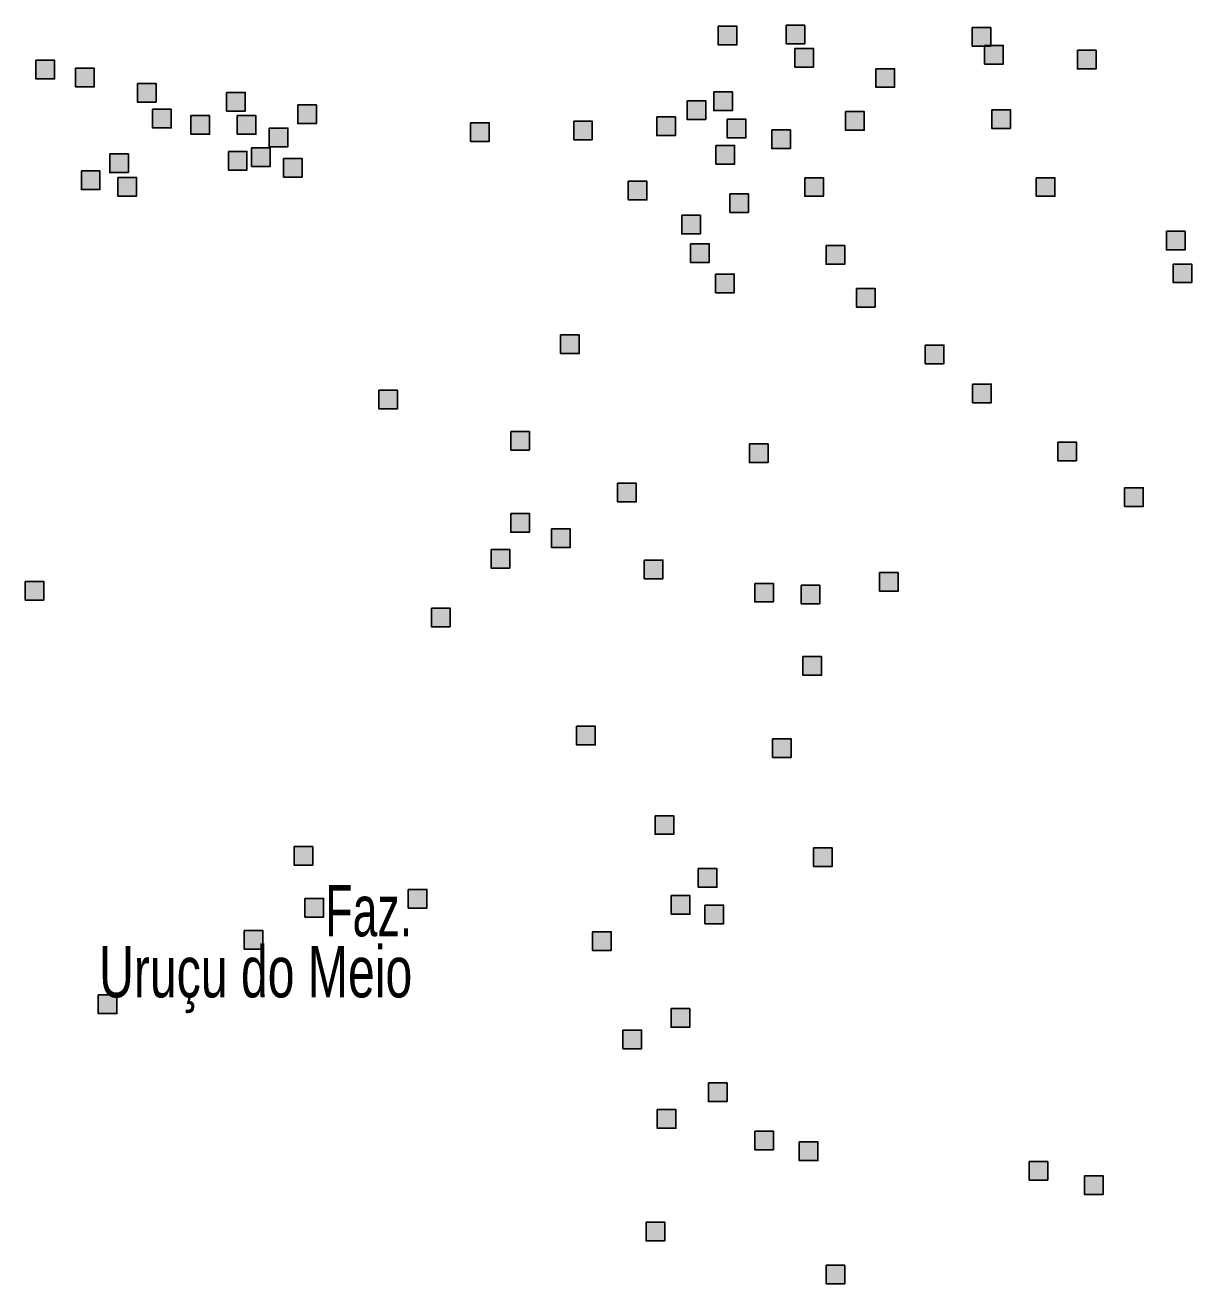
# Model space of a CAD drawing. Extents: x 445.6 to 500, y 8618.1 to 8673.4.
# Drawn here: x 460.751 to 464.38, y 8626.549 to 8630.464 of the extents above; entities that cross this region are included whole.
import ezdxf
from ezdxf.enums import TextEntityAlignment as Align

# ---------------------------------------------------------------- set-up
doc = ezdxf.new("R2010")
doc.units = 0
doc.header["$LTSCALE"] = 0.064
doc.layers.add('2', color=7, linetype='Continuous', lineweight=25)
doc.layers.add('61', color=7, linetype='Continuous')

msp = doc.modelspace()

# ---------------------------------------------------------------- hatches: boundary and pattern name
at = {"layer": '2'}
for points in [[(462.9071, 8630.4607), (462.9651, 8630.4607), (462.9651, 8630.4027), (462.9071, 8630.4027)], [(463.1178, 8630.4641), (463.1758, 8630.4641), (463.1758, 8630.4061), (463.1178, 8630.4061)], [(463.6966, 8630.4567), (463.7546, 8630.4567), (463.7546, 8630.3987), (463.6966, 8630.3987)], [(463.1455, 8630.3919), (463.2035, 8630.3919), (463.2035, 8630.3339), (463.1455, 8630.3339)], [(463.7354, 8630.4011), (463.7934, 8630.4011), (463.7934, 8630.3431), (463.7354, 8630.3431)], [(464.0241, 8630.3862), (464.0821, 8630.3862), (464.0821, 8630.3282), (464.0241, 8630.3282)], [(460.7846, 8630.3551), (460.8426, 8630.3551), (460.8426, 8630.2971), (460.7846, 8630.2971)], [(460.9081, 8630.3303), (460.9661, 8630.3303), (460.9661, 8630.2723), (460.9081, 8630.2723)], [(463.3973, 8630.3288), (463.4553, 8630.3288), (463.4553, 8630.2708), (463.3973, 8630.2708)], [(461.1005, 8630.2828), (461.1585, 8630.2828), (461.1585, 8630.2248), (461.1005, 8630.2248)], [(461.3776, 8630.255), (461.4356, 8630.255), (461.4356, 8630.197), (461.3776, 8630.197)], [(462.893, 8630.2566), (462.951, 8630.2566), (462.951, 8630.1986), (462.893, 8630.1986)], [(461.5992, 8630.2161), (461.6572, 8630.2161), (461.6572, 8630.1581), (461.5992, 8630.1581)], [(462.8099, 8630.2288), (462.8679, 8630.2288), (462.8679, 8630.1708), (462.8099, 8630.1708)], [(461.1473, 8630.2027), (461.2053, 8630.2027), (461.2053, 8630.1447), (461.1473, 8630.1447)], [(461.2667, 8630.1828), (461.3247, 8630.1828), (461.3247, 8630.1248), (461.2667, 8630.1248)], [(461.4108, 8630.1828), (461.4688, 8630.1828), (461.4688, 8630.1248), (461.4108, 8630.1248)], [(462.7157, 8630.1788), (462.7737, 8630.1788), (462.7737, 8630.1208), (462.7157, 8630.1208)], [(462.9348, 8630.1717), (462.9928, 8630.1717), (462.9928, 8630.1137), (462.9348, 8630.1137)], [(463.3031, 8630.1955), (463.3611, 8630.1955), (463.3611, 8630.1375), (463.3031, 8630.1375)], [(463.7575, 8630.201), (463.8155, 8630.201), (463.8155, 8630.143), (463.7575, 8630.143)], [(461.5106, 8630.1439), (461.5686, 8630.1439), (461.5686, 8630.0859), (461.5106, 8630.0859)], [(462.1368, 8630.1605), (462.1948, 8630.1605), (462.1948, 8630.1025), (462.1368, 8630.1025)], [(462.4572, 8630.1655), (462.5152, 8630.1655), (462.5152, 8630.1075), (462.4572, 8630.1075)], [(463.0733, 8630.1383), (463.1313, 8630.1383), (463.1313, 8630.0803), (463.0733, 8630.0803)], [(462.8998, 8630.0902), (462.9578, 8630.0902), (462.9578, 8630.0322), (462.8998, 8630.0322)], [(461.0143, 8630.0637), (461.0723, 8630.0637), (461.0723, 8630.0057), (461.0143, 8630.0057)], [(461.3831, 8630.0716), (461.4411, 8630.0716), (461.4411, 8630.0136), (461.3831, 8630.0136)], [(461.4552, 8630.0827), (461.5132, 8630.0827), (461.5132, 8630.0247), (461.4552, 8630.0247)], [(461.5549, 8630.0494), (461.6129, 8630.0494), (461.6129, 8629.9914), (461.5549, 8629.9914)], [(460.9259, 8630.0106), (460.9839, 8630.0106), (460.9839, 8629.9526), (460.9259, 8629.9526)], [(461.0399, 8629.9904), (461.0979, 8629.9904), (461.0979, 8629.9324), (461.0399, 8629.9324)], [(462.627, 8629.9787), (462.685, 8629.9787), (462.685, 8629.9207), (462.627, 8629.9207)], [(463.1757, 8629.9898), (463.2337, 8629.9898), (463.2337, 8629.9318), (463.1757, 8629.9318)], [(463.8961, 8629.9898), (463.9541, 8629.9898), (463.9541, 8629.9318), (463.8961, 8629.9318)], [(462.9429, 8629.9398), (463.0009, 8629.9398), (463.0009, 8629.8818), (462.9429, 8629.8818)], [(462.7933, 8629.8731), (462.8513, 8629.8731), (462.8513, 8629.8151), (462.7933, 8629.8151)], [(464.3006, 8629.8231), (464.3586, 8629.8231), (464.3586, 8629.7651), (464.3006, 8629.7651)], [(462.821, 8629.7842), (462.879, 8629.7842), (462.879, 8629.7262), (462.821, 8629.7262)], [(463.2422, 8629.7786), (463.3002, 8629.7786), (463.3002, 8629.7206), (463.2422, 8629.7206)], [(464.3218, 8629.7213), (464.3798, 8629.7213), (464.3798, 8629.6633), (464.3218, 8629.6633)], [(462.8986, 8629.6897), (462.9566, 8629.6897), (462.9566, 8629.6317), (462.8986, 8629.6317)], [(463.3364, 8629.6452), (463.3944, 8629.6452), (463.3944, 8629.5872), (463.3364, 8629.5872)], [(462.4164, 8629.5007), (462.4744, 8629.5007), (462.4744, 8629.4427), (462.4164, 8629.4427)], [(463.5506, 8629.4691), (463.6086, 8629.4691), (463.6086, 8629.4111), (463.5506, 8629.4111)], [(463.6981, 8629.348), (463.7561, 8629.348), (463.7561, 8629.29), (463.6981, 8629.29)], [(461.8512, 8629.3284), (461.9092, 8629.3284), (461.9092, 8629.2704), (461.8512, 8629.2704)], [(462.2613, 8629.2005), (462.3193, 8629.2005), (462.3193, 8629.1425), (462.2613, 8629.1425)], [(463.0039, 8629.1616), (463.0619, 8629.1616), (463.0619, 8629.1036), (463.0039, 8629.1036)], [(463.9626, 8629.1672), (464.0206, 8629.1672), (464.0206, 8629.1092), (463.9626, 8629.1092)], [(462.5938, 8629.0394), (462.6518, 8629.0394), (462.6518, 8628.9814), (462.5938, 8628.9814)], [(464.1709, 8629.0252), (464.2289, 8629.0252), (464.2289, 8628.9672), (464.1709, 8628.9672)], [(462.2613, 8628.9449), (462.3193, 8628.9449), (462.3193, 8628.8869), (462.2613, 8628.8869)], [(462.3887, 8628.8974), (462.4467, 8628.8974), (462.4467, 8628.8394), (462.3887, 8628.8394)], [(462.2003, 8628.8337), (462.2583, 8628.8337), (462.2583, 8628.7757), (462.2003, 8628.7757)], [(462.6769, 8628.8004), (462.7349, 8628.8004), (462.7349, 8628.7424), (462.6769, 8628.7424)], [(463.4084, 8628.7615), (463.4664, 8628.7615), (463.4664, 8628.7035), (463.4084, 8628.7035)], [(460.7512, 8628.7341), (460.8092, 8628.7341), (460.8092, 8628.6761), (460.7512, 8628.6761)], [(463.0205, 8628.7281), (463.0785, 8628.7281), (463.0785, 8628.6701), (463.0205, 8628.6701)], [(463.1646, 8628.7225), (463.2226, 8628.7225), (463.2226, 8628.6645), (463.1646, 8628.6645)], [(462.0147, 8628.6512), (462.0727, 8628.6512), (462.0727, 8628.5932), (462.0147, 8628.5932)], [(463.1701, 8628.5002), (463.2281, 8628.5002), (463.2281, 8628.4422), (463.1701, 8628.4422)], [(462.4663, 8628.2835), (462.5243, 8628.2835), (462.5243, 8628.2255), (462.4663, 8628.2255)], [(463.0759, 8628.2445), (463.1339, 8628.2445), (463.1339, 8628.1865), (463.0759, 8628.1865)], [(462.7102, 8628.0055), (462.7682, 8628.0055), (462.7682, 8627.9475), (462.7102, 8627.9475)], [(461.5879, 8627.9094), (461.6459, 8627.9094), (461.6459, 8627.8514), (461.5879, 8627.8514)], [(463.2034, 8627.9055), (463.2614, 8627.9055), (463.2614, 8627.8475), (463.2034, 8627.8475)], [(462.8446, 8627.8411), (462.9026, 8627.8411), (462.9026, 8627.7831), (462.8446, 8627.7831)], [(461.6211, 8627.7482), (461.6791, 8627.7482), (461.6791, 8627.6902), (461.6211, 8627.6902)], [(461.9425, 8627.776), (462.0005, 8627.776), (462.0005, 8627.718), (461.9425, 8627.718)], [(462.7608, 8627.7571), (462.8188, 8627.7571), (462.8188, 8627.6991), (462.7608, 8627.6991)], [(462.8653, 8627.7276), (462.9233, 8627.7276), (462.9233, 8627.6696), (462.8653, 8627.6696)], [(461.4327, 8627.6482), (461.4907, 8627.6482), (461.4907, 8627.5902), (461.4327, 8627.5902)], [(462.5162, 8627.6443), (462.5742, 8627.6443), (462.5742, 8627.5863), (462.5162, 8627.5863)], [(460.9783, 8627.4481), (461.0363, 8627.4481), (461.0363, 8627.3901), (460.9783, 8627.3901)], [(462.76, 8627.4053), (462.818, 8627.4053), (462.818, 8627.3473), (462.76, 8627.3473)], [(462.6104, 8627.3386), (462.6684, 8627.3386), (462.6684, 8627.2806), (462.6104, 8627.2806)], [(462.8764, 8627.1744), (462.9344, 8627.1744), (462.9344, 8627.1164), (462.8764, 8627.1164)], [(462.7172, 8627.0912), (462.7752, 8627.0912), (462.7752, 8627.0332), (462.7172, 8627.0332)], [(463.0205, 8627.0243), (463.0785, 8627.0243), (463.0785, 8626.9663), (463.0205, 8626.9663)], [(463.159, 8626.991), (463.217, 8626.991), (463.217, 8626.933), (463.159, 8626.933)], [(463.8739, 8626.9299), (463.9319, 8626.9299), (463.9319, 8626.8719), (463.8739, 8626.8719)], [(464.0457, 8626.8854), (464.1037, 8626.8854), (464.1037, 8626.8274), (464.0457, 8626.8274)], [(462.6824, 8626.7409), (462.7404, 8626.7409), (462.7404, 8626.6829), (462.6824, 8626.6829)], [(463.2422, 8626.6075), (463.3002, 8626.6075), (463.3002, 8626.5495), (463.2422, 8626.5495)]]:
    msp.add_hatch(color=256, dxfattribs=at).paths.add_polyline_path(points)

# ---------------------------------------------------------------- linework, layer by layer
for points in [[(462.9071, 8630.4607), (462.9651, 8630.4607), (462.9651, 8630.4027), (462.9071, 8630.4027)], [(463.1178, 8630.4641), (463.1758, 8630.4641), (463.1758, 8630.4061), (463.1178, 8630.4061)], [(463.6966, 8630.4567), (463.7546, 8630.4567), (463.7546, 8630.3987), (463.6966, 8630.3987)], [(463.1455, 8630.3919), (463.2035, 8630.3919), (463.2035, 8630.3339), (463.1455, 8630.3339)], [(463.7354, 8630.4011), (463.7934, 8630.4011), (463.7934, 8630.3431), (463.7354, 8630.3431)], [(464.0241, 8630.3862), (464.0821, 8630.3862), (464.0821, 8630.3282), (464.0241, 8630.3282)], [(460.7846, 8630.3551), (460.8426, 8630.3551), (460.8426, 8630.2971), (460.7846, 8630.2971)], [(460.9081, 8630.3303), (460.9661, 8630.3303), (460.9661, 8630.2723), (460.9081, 8630.2723)], [(463.3973, 8630.3288), (463.4553, 8630.3288), (463.4553, 8630.2708), (463.3973, 8630.2708)], [(461.1005, 8630.2828), (461.1585, 8630.2828), (461.1585, 8630.2248), (461.1005, 8630.2248)], [(461.3776, 8630.255), (461.4356, 8630.255), (461.4356, 8630.197), (461.3776, 8630.197)], [(462.893, 8630.2566), (462.951, 8630.2566), (462.951, 8630.1986), (462.893, 8630.1986)], [(461.5992, 8630.2161), (461.6572, 8630.2161), (461.6572, 8630.1581), (461.5992, 8630.1581)], [(462.8099, 8630.2288), (462.8679, 8630.2288), (462.8679, 8630.1708), (462.8099, 8630.1708)], [(461.1473, 8630.2027), (461.2053, 8630.2027), (461.2053, 8630.1447), (461.1473, 8630.1447)], [(461.2667, 8630.1828), (461.3247, 8630.1828), (461.3247, 8630.1248), (461.2667, 8630.1248)], [(461.4108, 8630.1828), (461.4688, 8630.1828), (461.4688, 8630.1248), (461.4108, 8630.1248)], [(462.7157, 8630.1788), (462.7737, 8630.1788), (462.7737, 8630.1208), (462.7157, 8630.1208)], [(462.9348, 8630.1717), (462.9928, 8630.1717), (462.9928, 8630.1137), (462.9348, 8630.1137)], [(463.3031, 8630.1955), (463.3611, 8630.1955), (463.3611, 8630.1375), (463.3031, 8630.1375)], [(463.7575, 8630.201), (463.8155, 8630.201), (463.8155, 8630.143), (463.7575, 8630.143)], [(461.5106, 8630.1439), (461.5686, 8630.1439), (461.5686, 8630.0859), (461.5106, 8630.0859)], [(462.1368, 8630.1605), (462.1948, 8630.1605), (462.1948, 8630.1025), (462.1368, 8630.1025)], [(462.4572, 8630.1655), (462.5152, 8630.1655), (462.5152, 8630.1075), (462.4572, 8630.1075)], [(463.0733, 8630.1383), (463.1313, 8630.1383), (463.1313, 8630.0803), (463.0733, 8630.0803)], [(462.8998, 8630.0902), (462.9578, 8630.0902), (462.9578, 8630.0322), (462.8998, 8630.0322)], [(461.0143, 8630.0637), (461.0723, 8630.0637), (461.0723, 8630.0057), (461.0143, 8630.0057)], [(461.3831, 8630.0716), (461.4411, 8630.0716), (461.4411, 8630.0136), (461.3831, 8630.0136)], [(461.4552, 8630.0827), (461.5132, 8630.0827), (461.5132, 8630.0247), (461.4552, 8630.0247)], [(461.5549, 8630.0494), (461.6129, 8630.0494), (461.6129, 8629.9914), (461.5549, 8629.9914)], [(460.9259, 8630.0106), (460.9839, 8630.0106), (460.9839, 8629.9526), (460.9259, 8629.9526)], [(461.0399, 8629.9904), (461.0979, 8629.9904), (461.0979, 8629.9324), (461.0399, 8629.9324)], [(462.627, 8629.9787), (462.685, 8629.9787), (462.685, 8629.9207), (462.627, 8629.9207)], [(463.1757, 8629.9898), (463.2337, 8629.9898), (463.2337, 8629.9318), (463.1757, 8629.9318)], [(463.8961, 8629.9898), (463.9541, 8629.9898), (463.9541, 8629.9318), (463.8961, 8629.9318)], [(462.9429, 8629.9398), (463.0009, 8629.9398), (463.0009, 8629.8818), (462.9429, 8629.8818)], [(462.7933, 8629.8731), (462.8513, 8629.8731), (462.8513, 8629.8151), (462.7933, 8629.8151)], [(464.3006, 8629.8231), (464.3586, 8629.8231), (464.3586, 8629.7651), (464.3006, 8629.7651)], [(462.821, 8629.7842), (462.879, 8629.7842), (462.879, 8629.7262), (462.821, 8629.7262)], [(463.2422, 8629.7786), (463.3002, 8629.7786), (463.3002, 8629.7206), (463.2422, 8629.7206)], [(464.3218, 8629.7213), (464.3798, 8629.7213), (464.3798, 8629.6633), (464.3218, 8629.6633)], [(462.8986, 8629.6897), (462.9566, 8629.6897), (462.9566, 8629.6317), (462.8986, 8629.6317)], [(463.3364, 8629.6452), (463.3944, 8629.6452), (463.3944, 8629.5872), (463.3364, 8629.5872)], [(462.4164, 8629.5007), (462.4744, 8629.5007), (462.4744, 8629.4427), (462.4164, 8629.4427)], [(463.5506, 8629.4691), (463.6086, 8629.4691), (463.6086, 8629.4111), (463.5506, 8629.4111)], [(463.6981, 8629.348), (463.7561, 8629.348), (463.7561, 8629.29), (463.6981, 8629.29)], [(461.8512, 8629.3284), (461.9092, 8629.3284), (461.9092, 8629.2704), (461.8512, 8629.2704)], [(462.2613, 8629.2005), (462.3193, 8629.2005), (462.3193, 8629.1425), (462.2613, 8629.1425)], [(463.0039, 8629.1616), (463.0619, 8629.1616), (463.0619, 8629.1036), (463.0039, 8629.1036)], [(463.9626, 8629.1672), (464.0206, 8629.1672), (464.0206, 8629.1092), (463.9626, 8629.1092)], [(462.5938, 8629.0394), (462.6518, 8629.0394), (462.6518, 8628.9814), (462.5938, 8628.9814)], [(464.1709, 8629.0252), (464.2289, 8629.0252), (464.2289, 8628.9672), (464.1709, 8628.9672)], [(462.2613, 8628.9449), (462.3193, 8628.9449), (462.3193, 8628.8869), (462.2613, 8628.8869)], [(462.3887, 8628.8974), (462.4467, 8628.8974), (462.4467, 8628.8394), (462.3887, 8628.8394)], [(462.2003, 8628.8337), (462.2583, 8628.8337), (462.2583, 8628.7757), (462.2003, 8628.7757)], [(462.6769, 8628.8004), (462.7349, 8628.8004), (462.7349, 8628.7424), (462.6769, 8628.7424)], [(463.4084, 8628.7615), (463.4664, 8628.7615), (463.4664, 8628.7035), (463.4084, 8628.7035)], [(460.7512, 8628.7341), (460.8092, 8628.7341), (460.8092, 8628.6761), (460.7512, 8628.6761)], [(463.0205, 8628.7281), (463.0785, 8628.7281), (463.0785, 8628.6701), (463.0205, 8628.6701)], [(463.1646, 8628.7225), (463.2226, 8628.7225), (463.2226, 8628.6645), (463.1646, 8628.6645)], [(462.0147, 8628.6512), (462.0727, 8628.6512), (462.0727, 8628.5932), (462.0147, 8628.5932)], [(463.1701, 8628.5002), (463.2281, 8628.5002), (463.2281, 8628.4422), (463.1701, 8628.4422)], [(462.4663, 8628.2835), (462.5243, 8628.2835), (462.5243, 8628.2255), (462.4663, 8628.2255)], [(463.0759, 8628.2445), (463.1339, 8628.2445), (463.1339, 8628.1865), (463.0759, 8628.1865)], [(462.7102, 8628.0055), (462.7682, 8628.0055), (462.7682, 8627.9475), (462.7102, 8627.9475)], [(461.5879, 8627.9094), (461.6459, 8627.9094), (461.6459, 8627.8514), (461.5879, 8627.8514)], [(463.2034, 8627.9055), (463.2614, 8627.9055), (463.2614, 8627.8475), (463.2034, 8627.8475)], [(462.8446, 8627.8411), (462.9026, 8627.8411), (462.9026, 8627.7831), (462.8446, 8627.7831)], [(461.6211, 8627.7482), (461.6791, 8627.7482), (461.6791, 8627.6902), (461.6211, 8627.6902)], [(461.9425, 8627.776), (462.0005, 8627.776), (462.0005, 8627.718), (461.9425, 8627.718)], [(462.7608, 8627.7571), (462.8188, 8627.7571), (462.8188, 8627.6991), (462.7608, 8627.6991)], [(462.8653, 8627.7276), (462.9233, 8627.7276), (462.9233, 8627.6696), (462.8653, 8627.6696)], [(461.4327, 8627.6482), (461.4907, 8627.6482), (461.4907, 8627.5902), (461.4327, 8627.5902)], [(462.5162, 8627.6443), (462.5742, 8627.6443), (462.5742, 8627.5863), (462.5162, 8627.5863)], [(460.9783, 8627.4481), (461.0363, 8627.4481), (461.0363, 8627.3901), (460.9783, 8627.3901)], [(462.76, 8627.4053), (462.818, 8627.4053), (462.818, 8627.3473), (462.76, 8627.3473)], [(462.6104, 8627.3386), (462.6684, 8627.3386), (462.6684, 8627.2806), (462.6104, 8627.2806)], [(462.8764, 8627.1744), (462.9344, 8627.1744), (462.9344, 8627.1164), (462.8764, 8627.1164)], [(462.7172, 8627.0912), (462.7752, 8627.0912), (462.7752, 8627.0332), (462.7172, 8627.0332)], [(463.0205, 8627.0243), (463.0785, 8627.0243), (463.0785, 8626.9663), (463.0205, 8626.9663)], [(463.159, 8626.991), (463.217, 8626.991), (463.217, 8626.933), (463.159, 8626.933)], [(463.8739, 8626.9299), (463.9319, 8626.9299), (463.9319, 8626.8719), (463.8739, 8626.8719)], [(464.0457, 8626.8854), (464.1037, 8626.8854), (464.1037, 8626.8274), (464.0457, 8626.8274)], [(462.6824, 8626.7409), (462.7404, 8626.7409), (462.7404, 8626.6829), (462.6824, 8626.6829)], [(463.2422, 8626.6075), (463.3002, 8626.6075), (463.3002, 8626.5495), (463.2422, 8626.5495)]]:
    msp.add_lwpolyline(points, close=True, dxfattribs=at)

# ---------------------------------------------------------------- texts
at = {"layer": '61'}
for s, width, p in [('Faz.', 0.65, (461.9551, 8627.6304)), ('Uruçu do Meio', 0.7, (461.9551, 8627.4404))]:
    msp.add_text(s, height=0.16, dxfattribs=dict(at, width=width)).set_placement(p, align=Align.RIGHT)

doc.saveas('drawing.dxf')
